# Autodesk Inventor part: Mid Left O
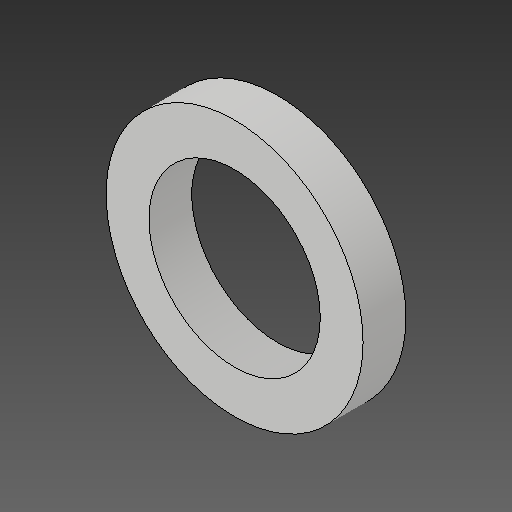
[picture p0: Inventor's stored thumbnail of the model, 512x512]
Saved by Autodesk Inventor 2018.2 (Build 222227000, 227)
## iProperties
Created: 2018-03
Part Number: Mid Left O
Material: Generic
Document SubType Name: Modeling
Designer: PeterMaxwell-Stewart
Mass: 1.9635 g
Surface Area: 15.708 cm^2
Volume: 1.9635 cm^3
Density: 1 g/cm^3
Appearance: Default
Author: PeterMaxwell-Stewart
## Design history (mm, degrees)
derived "O's and X's.ipt"
feature "Mid Left O::O's and X's.ipt" dims "d0" = 10
tag "TaggingFeature1"
body "Solid1"
